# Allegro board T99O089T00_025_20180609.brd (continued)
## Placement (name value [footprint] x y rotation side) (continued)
C118  47uF  [C-0805-H1_35]  269.66 135.65 90 top
C119  1uF  [S-C-0402]  206.9 173.93 0 top
C120  0.1uF  [S-C-0402]  203.54 173.93 0 bottom
C121  0.1uF  [S-C-0402]  202.58 173.93 0 bottom
C122  1nF  [S-C-0402]  208.37 173.93 180 bottom
C123  0.1uF  [S-C-0402]  210.76 173.93 180 top
C124  1uF  [S-C-0402]  207.86 173.93 0 top
C125  0.1uF  [S-C-0402]  212.69 173.93 180 top
C126  0.1uF  [S-C-0402]  206.44 173.93 0 bottom
C127  1nF  [S-C-0402]  211.27 173.93 180 bottom
C128  0.1uF  [S-C-0402]  201.61 173.93 0 bottom
C129  1uF  [S-C-0402]  201.61 173.93 0 top
C130  0.1uF  [S-C-0402]  219.45 173.93 180 top
C131  0.1uF  [S-C-0402]  217.06 173.93 0 bottom
C132  1nF  [S-C-0402]  210.3 173.93 180 bottom
C133  0.1uF  [S-C-0402]  216.55 173.93 180 top
C134  1uF  [S-C-0402]  239.37 173.93 0 top
C135  0.1uF  [S-C-0402]  215.13 173.93 0 bottom
C136  0.1uF  [S-C-0402]  214.62 173.93 180 top
C137  1nF  [S-C-0402]  213.2 173.93 180 bottom
C138  0.1uF  [S-C-0402]  219.95 173.93 0 bottom
C139  47uF  [C-0805-H1_35]  231.79 173.49 180 top
C140  1uF  [S-C-0402]  230.23 173.93 0 top
C141  0.1uF  [S-C-0402]  231.2 173.93 0 bottom
C142  0.1uF  [S-C-0402]  235.06 173.93 0 bottom
C143  1nF  [S-C-0402]  242.27 173.93 0 top
C144  0.1uF  [S-C-0402]  230.23 173.93 0 bottom
C145  1uF  [S-C-0402]  209.79 173.93 0 top
C146  0.1uF  [S-C-0402]  228.35 173.91 180 top
C147  0.1uF  [S-C-0402]  228.32 173.94 0 bottom
C148  1nF  [S-C-0402]  236.48 173.93 0 top
C149  0.1uF  [S-C-0402]  236.99 173.93 0 bottom
C150  1uF  [S-C-0402]  270.24 131.92 270 top
C151  0.1uF  [S-C-0402]  238.92 173.93 0 bottom
C152  0.1uF  [S-C-0402]  239.88 173.93 0 bottom
C153  1nF  [S-C-0402]  229.29 173.91 0 top
C154  0.1uF  [S-C-0402]  232.16 173.93 0 bottom
C155  1uF  [S-C-0402]  244.2 173.93 0 top
C156  0.1uF  [S-C-0402]  235.51 173.93 180 top
C157  0.1uF  [S-C-0402]  270.24 118.41 90 top
C158  1nF  [S-C-0402]  270.24 128.52 90 bottom
C159  0.1uF  [S-C-0402]  244.71 173.93 0 bottom
C160  47uF  [C-0805-H1_35]  203.17 173.48 180 top
C161  1uF  [S-C-0402]  238.41 173.93 0 top
C162  0.1uF  [S-C-0402]  242.78 173.93 0 bottom
C163  0.1uF  [S-C-0402]  270.24 126.13 90 top
C164  1nF  [S-C-0402]  270.24 127.55 90 bottom
C165  0.1uF  [S-C-0402]  270.24 135.27 270 bottom
C166  1uF  [S-C-0402]  270.24 137.2 270 top
C167  0.1uF  [S-C-0402]  270.24 137.2 270 bottom
C168  0.1uF  [S-C-0402]  270.24 136.24 270 bottom
C169  1nF  [S-C-0402]  270.24 125.62 90 bottom
C170  0.1uF  [S-C-0402]  270.24 132.38 270 bottom
C171  1uF  [S-C-0402]  270.24 129.02 270 top
C172  0.1uF  [S-C-0402]  270.24 121.3 90 top
C173  0.1uF  [S-C-0402]  270.24 121.76 270 bottom
C174  1nF  [S-C-0402]  241.3 173.93 0 top
C175  0.1uF  [S-C-0402]  270.24 118.86 270 bottom
C176  1uF  [S-C-0402]  270.24 130.96 270 top
C177  0.1uF  [S-C-0402]  270.24 124.2 90 top
C178  0.1uF  [S-C-0402]  270.24 128.06 90 top
C179  1nF  [S-C-0402]  270.24 130.45 90 bottom
C180  0.1uF  [S-C-0402]  270.24 123.69 270 bottom
C181  47uF  [C-0805-H1_35]  205.32 173.48 0 top
C182  1uF  [S-C-0402]  216.09 173.93 0 bottom
C183  0.1uF  [S-C-0402]  245.17 173.93 0 top
C184  0.1uF  [S-C-0402]  270.24 120.34 270 top
C185  1nF  [S-C-0402]  205.48 173.93 0 bottom
C186  0.1uF  [S-C-0402]  270.24 122.27 270 top
C187  1uF  [S-C-0402]  217.51 173.93 180 top
C188  0.1uF  [S-C-0402]  218.48 173.93 0 top
C189  0.1uF  [S-C-0402]  214.16 173.93 180 bottom
C190  1nF  [S-C-0402]  200.65 173.93 0 bottom
C191  0.1uF  [S-C-0402]  246.13 173.93 0 top
C192  1uF  [S-C-0402]  200.65 173.93 180 top
C193  0.1uF  [S-C-0402]  247.09 173.94 0 top
C194  0.1uF  [S-C-0402]  233.13 173.93 180 bottom
C195  1nF  [S-C-0402]  199.68 173.93 0 bottom
C196  0.1uF  [S-C-0402]  234.09 173.93 180 bottom
C197  1uF  [S-C-0402]  199.68 173.93 180 top
C198  0.1uF  [S-C-0402]  240.85 173.93 180 bottom
C199  0.1uF  [S-C-0402]  237.95 173.93 180 bottom
C200  1nF  [S-C-0402]  229.26 173.94 0 bottom
C201  0.1uF  [S-C-0402]  218.99 173.93 180 bottom
C202  47uF  [C-0805-H1_35]  269.66 133.5 270 top
C203  1uF  [S-C-0402]  240.34 173.93 180 top
C204  0.1uF  [S-C-0402]  230.76 171.07 0 bottom
C205  0.1uF  [S-C-0402]  229.74 171.07 0 bottom
C206  1nF  [S-C-0402]  207.41 173.93 0 bottom
C207  0.1uF  [S-C-0402]  220.41 173.93 0 top
C208  1uF  [S-C-0402]  230.1 171.09 0 top
C209  0.1uF  [S-C-0402]  218.02 173.93 180 bottom
C210  0.1uF  [S-C-0402]  212.23 173.93 180 bottom
C211  1nF  [S-C-0402]  241.81 173.93 0 bottom
C212  0.1uF  [S-C-0402]  213.65 173.93 0 top
C213  1uF  [S-C-0402]  229.08 171.09 0 top
C214  0.1uF  [S-C-0402]  209.34 173.93 180 bottom
C215  0.1uF  [S-C-0402]  208.83 173.93 0 top
C216  1nF  [S-C-0402]  246.64 173.93 0 bottom
C217  0.1uF  [S-C-0402]  204.51 173.93 180 bottom
C218  1uF  [S-C-0402]  270.24 123.23 90 top
C219  0.1uF  [S-C-0402]  270.24 134.31 90 bottom
C220  0.1uF  [S-C-0402]  270.24 127.09 270 top
C221  1nF  [S-C-0402]  245.67 173.93 0 bottom
C222  0.1uF  [S-C-0402]  270.24 124.66 90 bottom
C223  47uF  [C-0805-H1_35]  233.94 173.49 0 top
C224  1uF  [S-C-0402]  243.23 173.93 180 top
C225  0.1uF  [S-C-0402]  270.24 120.8 90 bottom
C226  0.1uF  [S-C-0402]  236.02 173.93 180 bottom
C227  1nF  [S-C-0402]  270.24 131.41 270 bottom
C228  0.1uF  [S-C-0402]  215.58 173.93 0 top
C229  1uF  [S-C-0402]  270.24 129.99 90 top
C230  0.1uF  [S-C-0402]  211.72 173.93 0 top
C231  0.1uF  [S-C-0402]  270.24 129.48 90 bottom
C232  1nF  [S-C-0402]  270.24 139.13 270 bottom
C233  0.1uF  [S-C-0402]  270.24 119.83 90 bottom
C234  1uF  [S-C-0402]  270.24 139.13 90 top
C235  0.1uF  [S-C-0402]  270.24 126.59 90 bottom
C236  0.1uF  [S-C-0402]  270.24 125.16 270 top
C237  1nF  [S-C-0402]  270.24 138.17 270 bottom
C238  0.1uF  [S-C-0402]  270.24 119.37 270 top
C239  1uF  [S-C-0402]  270.24 138.17 90 top
C240  0.1uF  [S-C-0402]  270.24 122.73 90 bottom
C241  0.1uF  [S-C-0402]  237.44 173.93 0 top
C242  1nF  [S-C-0402]  270.24 133.34 270 bottom
C243  0.1uF  [S-C-0402]  243.74 173.93 180 bottom
C244  330uF  [C-TAN-S7_3X4_3-H2]  185.29 101.02 270 top
C245  47uF  [C-0805-H1_35]  239.31 112.58 0 top
C246  1uF  [S-C-0402]  205.36 119.5 0 bottom
C247  0.1uF  [S-C-0402]  219.36 125.5 0 bottom
C248  0.1uF  [S-C-0402]  221.36 127.5 0 bottom
C249  1nF  [S-C-0402]  209.36 124.5 0 bottom
C250  1uF  [S-C-0402]  206.36 119.5 180 bottom
C251  0.1uF  [S-C-0402]  222.36 118.5 0 bottom
C252  1nF  [S-C-0402]  205.86 115 270 bottom
C253  0.1uF  [S-C-0402]  218.86 115 90 bottom
C254  1uF  [S-C-0402]  212.36 133.5 180 bottom
C255  0.1uF  [S-C-0402]  246.32 160.04 180 bottom
C256  0.1uF  [S-C-0402]  254.09 117.89 270 bottom
C257  1nF  [S-C-0402]  218.37 133.5 0 bottom
C258  1uF  [S-C-0402]  205.66 153.64 90 bottom
C259  0.1uF  [S-C-0402]  246.83 155.72 90 bottom
C260  1nF  [S-C-0402]  207.73 155.72 270 bottom
C261  0.1uF  [S-C-0402]  246.32 158.26 0 bottom
C262  47uF  [C-0805-H1_35]  266.43 121.23 0 top
C263  330uF  [C-TAN-S7_3X4_3-H2]  185.29 106.36 270 top
C264  22uF  [C-0805]  191.77 103.43 0 top
C265  0.1uF  [S-C-0402]  214.86 125.99 270 bottom
C266  0.1uF  [S-C-0402]  217.36 127.5 0 bottom
C267  0.1uF  [S-C-0402]  218.36 123.5 180 bottom
C268  1uF  [S-C-0402]  208.36 122.5 180 bottom
C269  0.1uF  [S-C-0402]  217.36 123.5 0 bottom
C270  0.1uF  [S-C-0402]  216.36 123.5 180 bottom
C271  1nF  [S-C-0402]  212.36 122.5 180 bottom
C272  0.1uF  [S-C-0402]  214.36 123.5 0 bottom
C273  0.1uF  [S-C-0402]  218.36 121.5 180 bottom
C274  0.1uF  [S-C-0402]  234.66 155.72 90 bottom
C275  0.1uF  [S-C-0402]  229.36 131.5 180 bottom
C276  330uF  [C-TAN-S7_3X4_3-H2]  194.2 142.01 90 bottom
C277  1uF  [S-C-0402]  209.36 116.5 180 bottom
C278  1nF  [S-C-0402]  212.36 117.5 0 bottom
C279  0.1uF  [S-C-0402]  218.36 118.5 0 bottom
C280  1uF  [S-C-0402]  211.43 153.64 270 bottom
C281  0.1uF  [S-C-0402]  229.36 134.5 180 bottom
C282  0.1uF  [S-C-0402]  230.84 160.71 270 bottom
C283  1nF  [S-C-0402]  219.37 135.5 0 bottom
C284  0.1uF  [S-C-0402]  232.58 153.64 270 bottom
C285  1uF  [S-C-0402]  211.86 136 90 bottom
C286  0.1uF  [S-C-0402]  231.36 126.5 180 bottom
C287  0.1uF  [S-C-0402]  229.36 125.5 180 bottom
C288  1nF  [S-C-0402]  220.37 131.5 0 bottom
C289  0.1uF  [S-C-0402]  222.36 135.5 180 bottom
C290  47uF  [C-0805-H1_35]  208.69 139.68 270 bottom
C291  0.1uF  [S-C-0402]  213.36 124.5 180 bottom
C292  1uF  [S-C-0402]  205.36 123.5 180 bottom
C293  0.1uF  [S-C-0402]  212.86 121 90 bottom
C294  0.1uF  [S-C-0402]  211.36 122.5 180 bottom
C295  1nF  [S-C-0402]  210.36 117.5 0 bottom
C296  0.1uF  [S-C-0402]  210.36 124.5 0 bottom
C297  1uF  [S-C-0402]  206.36 123.5 180 bottom
C298  0.1uF  [S-C-0402]  212.36 124.5 0 bottom
C299  0.1uF  [S-C-0402]  210.86 121 90 bottom
C300  1nF  [S-C-0402]  210.36 122.5 180 bottom
C301  0.1uF  [S-C-0402]  213.36 122.5 180 bottom
C302  1uF  [S-C-0402]  227.36 127.5 0 bottom
C303  0.1uF  [S-C-0402]  217.37 137.5 180 bottom
C304  0.1uF  [S-C-0402]  216.86 135 90 bottom
C305  1nF  [S-C-0402]  225.42 157.04 0 bottom
C306  0.1uF  [S-C-0402]  215.86 131 90 bottom
C307  1uF  [S-C-0402]  226.36 125.5 0 bottom
C308  0.1uF  [S-C-0402]  216.37 129.5 180 bottom
C309  0.1uF  [S-C-0402]  217.37 131.5 180 bottom
C310  1nF  [S-C-0402]  226.18 153.64 270 bottom
C311  0.1uF  [S-C-0402]  215.37 133.5 180 bottom
C312  47uF  [C-0805-H1_35]  203.23 139.68 270 bottom
C313  1uF  [S-C-0402]  225.86 124 90 bottom
C314  0.1uF  [S-C-0402]  210.39 159.54 270 bottom
C315  0.1uF  [S-C-0402]  210.09 156.66 270 bottom
C316  1nF  [S-C-0402]  226.36 131.5 0 bottom
C317  0.1uF  [S-C-0402]  212.23 160.77 90 bottom
C318  1uF  [S-C-0402]  217.83 153.64 90 bottom
C319  0.1uF  [S-C-0402]  210.45 160.54 270 bottom
C320  0.1uF  [S-C-0402]  210.37 137.5 180 bottom
C321  1nF  [S-C-0402]  226.98 160.85 90 bottom
C322  0.1uF  [S-C-0402]  210.36 135.5 0 bottom
C323  47uF  [C-0805-H1_35]  217.58 139.68 270 bottom
C324  330uF  [C-TAN-S7_3X4_3-H2]  192.63 161.81 0 top
C325  330uF  [C-TAN-S7_3X4_3-H2]  185.29 111.69 270 top
C326  47uF  [C-0805-H1_35]  191.77 112.25 0 top
C327  1uF  [S-C-0402]  217.36 119.5 180 bottom
C328  0.1uF  [S-C-0402]  211.86 115 270 bottom
C329  0.1uF  [S-C-0402]  211.86 116 90 bottom
C330  1nF  [S-C-0402]  215.36 123.5 0 bottom
C331  0.1uF  [S-C-0402]  211.36 117.5 0 bottom
C332  1uF  [S-C-0402]  217.36 117.5 180 bottom
C333  0.1uF  [S-C-0402]  212.36 119.5 180 bottom
C334  0.1uF  [S-C-0402]  210.36 119.5 180 bottom
C335  1nF  [S-C-0402]  211.36 124.5 0 bottom
C336  0.1uF  [S-C-0402]  211.36 119.5 0 bottom
C337  1uF  [S-C-0402]  227.36 133.5 0 bottom
C338  0.1uF  [S-C-0402]  206.86 136 270 bottom
C339  0.1uF  [S-C-0402]  207.23 160.04 180 bottom
C340  1nF  [S-C-0402]  225.42 159.94 0 bottom
C341  0.1uF  [S-C-0402]  207.23 158.26 0 bottom
C342  1uF  [S-C-0402]  225.36 126.5 180 bottom
C343  0.1uF  [S-C-0402]  205.79 160.71 90 bottom
C344  0.1uF  [S-C-0402]  206.37 133.5 0 bottom
C345  1nF  [S-C-0402]  227.86 124 90 bottom
C346  0.1uF  [S-C-0402]  207.36 137.5 180 bottom
C347  47uF  [C-0805-H1_35]  212.62 139.68 90 bottom
C348  330uF  [C-TAN-S7_3X4_3-H2]  245.62 107.5 90 top
C349  22uF  [C-0805]  239.5 105.51 180 top
C350  1uF  [S-C-0402]  214.86 122 90 bottom
C351  0.1uF  [S-C-0402]  209.36 127.5 180 bottom
C352  0.1uF  [S-C-0402]  206.36 117.5 180 bottom
C353  1nF  [S-C-0402]  222.36 114.5 180 bottom
C354  0.1uF  [S-C-0402]  209.36 119.5 0 bottom
C355  1uF  [S-C-0402]  214.86 118 90 bottom
C356  0.1uF  [S-C-0402]  209.36 122.5 180 bottom
C357  0.1uF  [S-C-0402]  207.36 122.5 180 bottom
C358  1nF  [S-C-0402]  218.36 127.5 0 bottom
C359  0.1uF  [S-C-0402]  208.86 115 90 bottom
C360  1uF  [S-C-0402]  226.36 137.49 0 bottom
C361  0.1uF  [S-C-0402]  201.37 135.5 0 bottom
C362  0.1uF  [S-C-0402]  208.86 132 90 bottom
C363  1nF  [S-C-0402]  229.36 128.5 0 bottom
C364  0.1uF  [S-C-0402]  208.36 133.5 180 bottom
C365  1uF  [S-C-0402]  227.36 135.5 0 bottom
C366  0.1uF  [S-C-0402]  203.37 133.5 0 bottom
C367  0.1uF  [S-C-0402]  251.55 129.05 0 bottom
C368  1nF  [S-C-0402]  231.36 132.5 0 bottom
C369  0.1uF  [S-C-0402]  254.09 129.56 270 bottom
C370  47uF  [C-0805-H1_35]  216.8 170.6 90 top
C371  0.1uF  [S-C-0402]  221.36 125.5 0 bottom
C372  1uF  [S-C-0402]  219.36 119.5 180 bottom
C373  0.1uF  [S-C-0402]  220.36 123.5 180 bottom
C374  0.1uF  [S-C-0402]  219.36 123.5 0 bottom
C375  1nF  [S-C-0402]  222.36 121.5 0 bottom
C376  0.1uF  [S-C-0402]  219.36 127.5 0 bottom
C377  1uF  [S-C-0402]  221.36 115.5 0 bottom
C378  0.1uF  [S-C-0402]  222.36 127.5 0 bottom
C379  0.1uF  [S-C-0402]  217.36 125.5 0 bottom
C380  1nF  [S-C-0402]  220.36 115.5 0 bottom
C381  0.1uF  [S-C-0402]  219.36 116.5 180 bottom
C382  1UF  [S-C-0402]  198.86 128 270 bottom
C383  0.1uF  [S-C-0402]  201.36 127.5 0 bottom
C384  0.1uF  [S-C-0402]  199.36 133.5 180 bottom
C385  1nF  [S-C-0402]  196.86 127 270 bottom
C386  0.1uF  [S-C-0402]  201.36 122.5 0 bottom
C387  1UF  [S-C-0402]  196.86 122 270 bottom
C388  22uF  [C-0805]  185.95 112.26 0 bottom
C389  330uF  [C-TAN-S7_3X4_3-H2]  245.75 102.11 90 top
C390  47uF  [C-0805-H1_35]  239.5 102.11 0 top
C391  1uF  [S-C-0402]  216.36 125.5 0 bottom
C392  0.1uF  [S-C-0402]  216.36 118.5 0 bottom
C393  0.1uF  [S-C-0402]  216.36 116.5 0 bottom
C394  1nF  [S-C-0402]  220.36 125.5 0 bottom
C395  0.1uF  [S-C-0402]  215.36 116.5 180 bottom
C396  1uF  [S-C-0402]  221.36 121.5 180 bottom
C397  0.1uF  [S-C-0402]  214.36 116.5 0 bottom
C398  0.1uF  [S-C-0402]  215.86 115 270 bottom
C399  1nF  [S-C-0402]  220.36 127.5 0 bottom
C400  0.1uF  [S-C-0402]  218.36 116.5 0 bottom
C401  0.1uF  [S-C-0402]  196.36 130.5 0 bottom
C402  0.1uF  [S-C-0402]  197.36 135.5 180 bottom
C403  0.1uF  [S-C-0402]  204.36 122.5 0 bottom
C404  1nF  [S-C-0402]  203.86 124 270 bottom
C405  0.1uF  [S-C-0402]  205.36 125.5 0 bottom
C406  10uF  [S-C-0402]  204.36 125.5 0 bottom
C407  330uF  [C-TAN-S7_3X4_3-H2]  245.62 113.36 90 top
C408  22uF  [C-0805]  191.77 107.37 180 top
C409  1uF  [S-C-0402]  219.36 121.5 180 bottom
C410  0.1uF  [S-C-0402]  214.36 114.5 0 bottom
C411  0.1uF  [S-C-0402]  217.36 115.5 0 bottom
C412  1nF  [S-C-0402]  220.36 121.5 0 bottom
C413  0.1uF  [S-C-0402]  210.36 127.5 0 bottom
C414  1uF  [S-C-0402]  222.86 116 90 bottom
C415  0.1uF  [S-C-0402]  211.36 127.5 180 bottom
C416  0.1uF  [S-C-0402]  213.36 126.5 180 bottom
C417  1nF  [S-C-0402]  218.36 125.5 0 bottom
C418  0.1uF  [S-C-0402]  223.36 118.5 0 bottom
C419  0.1uF  [S-C-0402]  203.36 126.5 0 bottom
C420  10uF  [S-C-0402]  204.36 127.5 180 bottom
C421  0.1uF  [S-C-0402]  193.76 133.88 90 bottom
C422  330uF  [C-TAN-S7_3X4_3-H2]  201.42 93.53 0 bottom
C423  330uF  [C-TAN-S7_3X4_3-H2]  217.11 90.1 270 bottom
C424  47uF  [C-0805-H1_35]  210.82 99.37 90 bottom
C425  1UF  [S-C-0402]  211.36 111.5 0 bottom
C426  0.1uF  [S-C-0402]  221.86 103 270 bottom
C427  0.1uF  [S-C-0402]  222.36 106.5 0 bottom
C428  1nF  [S-C-0402]  217.86 103 90 bottom
C429  0.1uF  [S-C-0402]  219.36 109.5 0 bottom
C430  0.1uF  [S-C-0402]  215.86 111 90 bottom
C431  0.1uF  [S-C-0402]  215.36 108.5 180 bottom
C432  1nF  [S-C-0402]  217.86 101 90 bottom
C433  0.1uF  [S-C-0402]  216.36 109.5 0 bottom
C434  1nF  [S-C-0402]  213.87 103.05 0 bottom
C435  0.1uF  [S-C-0402]  221.86 101 270 bottom
C436  1uF  [S-C-0402]  225.86 113 90 bottom
C437  0.1uF  [S-C-0402]  228.36 103.5 0 bottom
C438  1nF  [S-C-0402]  230.86 108 90 bottom
C439  1uF  [S-C-0402]  231.36 113.5 180 bottom
C440  0.1uF  [S-C-0402]  225.86 101 270 bottom
C441  0.1uF  [S-C-0402]  227.36 110.5 180 bottom
C442  1nF  [S-C-0402]  225.86 115 270 bottom
C443  330uF  [C-TAN-S7_3X4_3-H2]  238.68 102.02 270 bottom
C444  0.1uF  [S-C-0402]  226.86 108 270 bottom
C445  1nF  [S-C-0402]  224.86 114 90 bottom
C446  1uF  [S-C-0402]  224.36 118.5 180 bottom
C447  0.1uF  [S-C-0402]  225.86 103 270 bottom
C448  0.1uF  [S-C-0402]  229.86 101 270 bottom
C449  0.1uF  [S-C-0402]  226.86 106 270 bottom
C450  0.1uF  [S-C-0402]  226.86 117 270 bottom
C451  47uF  [C-0805-H1_35]  236.22 105.9 90 bottom
C452  47uF  [C-0805-H1_35]  215.9 99.37 90 bottom
C453  47uF  [C-0805-H1_35]  219.96 99.37 90 bottom
C454  1UF  [S-C-0402]  210.36 108.5 0 bottom
C455  0.1uF  [S-C-0402]  210.36 106.5 0 bottom
C456  0.1uF  [S-C-0402]  211.36 109.5 0 bottom
C457  1nF  [S-C-0402]  222.36 108.5 0 bottom
C458  0.1uF  [S-C-0402]  210.86 101 90 bottom
C459  1UF  [S-C-0402]  223.86 111 270 bottom
C460  0.1uF  [S-C-0402]  208.86 103 270 bottom
C461  0.1uF  [S-C-0402]  215.86 101 90 bottom
C462  1nF  [S-C-0402]  223.36 109.5 180 bottom
C463  0.1uF  [S-C-0402]  214.36 106.5 0 bottom
C464  1nF  [S-C-0402]  219.36 111.5 0 bottom
C465  0.1uF  [S-C-0402]  218.36 106.5 0 bottom
C466  1UF  [S-C-0402]  218.36 108.5 0 bottom
C467  330uF  [C-TAN-S7_3X4_3-H2]  206.88 93.53 0 bottom
C468  1uF  [S-C-0402]  226.35 118.5 0 bottom
C469  1nF  [S-C-0402]  229.36 118.5 180 bottom
C470  1uF  [S-C-0402]  233.36 114.5 0 bottom
C471  0.1uF  [S-C-0402]  229.86 103 270 bottom
C472  1nF  [S-C-0402]  229.36 114.5 180 bottom
C473  1uF  [S-C-0402]  231.36 118.5 0 bottom
C474  0.1uF  [S-C-0402]  231.36 106.5 0 bottom
C475  0.1uF  [S-C-0402]  227.86 105 90 bottom
C476  1nF  [S-C-0402]  233.36 118.5 0 bottom
C477  0.1uF  [S-C-0402]  231.86 105 270 bottom
C478  0.1uF  [S-C-0402]  228.36 117.5 0 bottom
C479  47uF  [C-0805-H1_35]  236.22 109.96 90 bottom
C480  1uF  [S-C-0402]  230.86 115 270 bottom
C481  0.1uF  [S-C-0402]  228.86 108 90 bottom
C482  1nF  [S-C-0402]  232.36 110.5 0 bottom
C483  1uF  [S-C-0402]  227.86 113 270 bottom
C484  0.1uF  [S-C-0402]  230.36 106.5 0 bottom
C485  0.1uF  [S-C-0402]  232.36 103.5 0 bottom
C486  1nF  [S-C-0402]  231.36 116.5 180 bottom
C487  0.1uF  [S-C-0402]  231.36 110.5 180 bottom
C488  0.1uF  [S-C-0402]  228.36 110.5 180 bottom
C489  47uF  [C-0805-H1_35]  236.22 107.93 90 bottom
C490  330uF  [C-TAN-S7_3X4_3-H2]  233.3 88.27 270 bottom
C491  330uF  [C-TAN-S7_3X4_3-H2]  225.91 95.2 270 bottom
C492  47uF  [C-0805-H1_35]  226.13 99.47 90 bottom
C493  1uF  [S-C-0402]  224.36 103.5 180 bottom
C494  0.1uF  [S-C-0402]  216.36 103.5 0 bottom
C495  0.1uF  [S-C-0402]  209.86 105 270 bottom
C496  1nF  [S-C-0402]  211.36 102.5 180 bottom
C497  0.1uF  [S-C-0402]  220.36 103.5 0 bottom
C498  1uF  [S-C-0402]  215.36 104.5 0 bottom
C499  0.1uF  [S-C-0402]  220.36 105.5 180 bottom
C500  0.1uF  [S-C-0402]  224.36 105.5 180 bottom
C501  1nF  [S-C-0402]  211.86 105 270 bottom
C502  0.1uF  [S-C-0402]  216.36 105.5 180 bottom
C503  1nF  [S-C-0402]  223.36 104.5 0 bottom
C504  0.1uF  [S-C-0402]  219.36 105.5 180 bottom
C505  10uF  [S-C-0402]  196.36 116.5 0 bottom
C506  1uF  [S-C-0402]  197.36 117.5 180 bottom
C507  0.1uF  [S-C-0402]  198.86 118 90 bottom
C508  0.1uF  [S-C-0402]  198.86 119 90 bottom
C509  1nF  [S-C-0402]  196.86 119 90 bottom
C510  22uF  [C-0805]  194.65 117.37 0 bottom
C511  0.1uF  [S-C-0402]  257.17 85.85 0 bottom
C512  330uF  [C-TAN-S7_3X4_3-H2]  241.35 88.49 180 bottom
C513  330uF  [C-TAN-S7_3X4_3-H2]  187.58 97.34 90 bottom
C514  47uF  [C-0805-H1_35]  194.56 103.43 180 bottom
C515  1uF  [S-C-0402]  204.36 109.5 0 bottom
C516  0.1uF  [S-C-0402]  197.86 105 90 bottom
C517  0.1uF  [S-C-0402]  200.36 109.5 180 bottom
C518  1nF  [S-C-0402]  198.86 101 270 bottom
C519  0.1uF  [S-C-0402]  196.36 102.5 0 bottom
C520  1uF  [S-C-0402]  198.86 108 270 bottom
C521  0.1uF  [S-C-0402]  196.36 104.5 180 bottom
C522  0.1uF  [S-C-0402]  206.86 103 90 bottom
C523  1nF  [S-C-0402]  195.36 112.5 180 bottom
C524  0.1uF  [S-C-0402]  197.36 115.5 180 bottom
C525  1nF  [S-C-0402]  196.86 110 270 bottom
C526  0.1uF  [S-C-0402]  198.86 114 90 bottom
C527  1uF  [S-C-0402]  195.4 120.54 0 bottom
C528  0.1uF  [S-C-0402]  196.86 120 90 bottom
C529  10uF  [C-0603S0]  194.15 120.8 180 bottom
C530  0.1uF  [S-C-0402]  254.67 100.65 180 bottom
C531  47uF  [C-0805-H1_35]  198.88 99.37 90 bottom
C532  47uF  [C-0805-H1_35]  194.69 106.86 0 bottom
C533  1uF  [S-C-0402]  196.36 108.5 180 bottom
C534  0.1uF  [S-C-0402]  201.86 106 90 bottom
C535  0.1uF  [S-C-0402]  204.36 104.5 180 bottom
C536  1nF  [S-C-0402]  197.86 106 270 bottom
C537  0.1uF  [S-C-0402]  200.86 101 270 bottom
C538  1uF  [S-C-0402]  205.86 110 270 bottom
C539  0.1uF  [S-C-0402]  199.36 115.5 180 bottom
C540  0.1uF  [S-C-0402]  205.86 106 90 bottom
C541  1nF  [S-C-0402]  200.36 104.5 0 bottom
C542  0.1uF  [S-C-0402]  202.36 108.5 180 bottom
C543  1nF  [S-C-0402]  198.86 103 270 bottom
C544  0.1uF  [S-C-0402]  201.86 110 90 bottom
C545  1uF  [S-C-0402]  216.86 122 90 bottom
C546  0.1uF  [S-C-0402]  216.86 121 90 bottom
C547  10uF  [C-0603S0]  234.4 120.8 180 bottom
C548  0.1uF  [S-C-0402]  5.11 80.31 90 top
C549  47uF  [C-0805-H1_35]  206.75 99.37 90 bottom
C550  47uF  [C-0805-H1_35]  202.82 99.37 90 bottom
C551  1uF  [S-C-0402]  202.86 115 90 bottom
C552  0.1uF  [S-C-0402]  202.86 113 90 bottom
C553  0.1uF  [S-C-0402]  204.36 107.5 0 bottom
C554  1nF  [S-C-0402]  202.86 103 270 bottom
C555  0.1uF  [S-C-0402]  206.86 101 90 bottom
C556  1uF  [S-C-0402]  200.86 114 90 bottom
C557  0.1uF  [S-C-0402]  206.86 108 90 bottom
C558  0.1uF  [S-C-0402]  200.86 113 270 bottom
C559  1nF  [S-C-0402]  201.86 105 270 bottom
C560  0.1uF  [S-C-0402]  204.86 114 90 bottom
C561  1nF  [S-C-0402]  197.36 113.5 180 bottom
C562  0.1uF  [S-C-0402]  205.86 105 90 bottom
C563  330uF  [C-TAN-S7_3X4_3-H2]  250.91 112.98 270 bottom
C564  330uF  [C-TAN-S7_3X4_3-H2]  241.94 125.45 0 bottom
C565  47uF  [C-0805-H1_35]  236.58 118.4 270 bottom
C566  1uF  [S-C-0402]  220.36 113.5 0 bottom
C567  0.1uF  [S-C-0402]  228.36 121.5 180 bottom
C568  0.1uF  [S-C-0402]  205.36 111.5 0 bottom
C569  1nF  [S-C-0402]  203.86 121 90 bottom
C570  0.1uF  [S-C-0402]  207.36 113.5 180 bottom
C571  1uF  [S-C-0402]  206.36 111.5 180 bottom
C572  0.1uF  [S-C-0402]  216.36 113.5 180 bottom
C573  0.1uF  [S-C-0402]  212.36 111.5 0 bottom
C574  1nF  [S-C-0402]  213.36 113.5 0 bottom
C575  0.1uF  [S-C-0402]  205.36 121.5 180 bottom
C576  1nF  [S-C-0402]  212.36 113.5 0 bottom
C577  0.1uF  [S-C-0402]  208.36 111.5 0 bottom
C578  1uF  [S-C-0402]  200.36 121.5 180 bottom
C579  0.1uF  [S-C-0402]  201.86 121 90 bottom
C580  10uF  [C-0603S0]  187.02 105.12 0 bottom
C581  0.1uF  [S-C-0402]  181.19 140.35 270 top
C582  1uF  [S-C-0402]  206.36 113.5 0 bottom
C583  0.1uF  [S-C-0402]  216.86 112 90 bottom
C584  0.1uF  [S-C-0402]  222.36 112.5 0 bottom
C585  1nF  [S-C-0402]  207.36 111.5 180 bottom
C586  0.1uF  [S-C-0402]  220.86 112 90 bottom
C587  1uF  [S-C-0402]  221.36 113.5 0 bottom
C588  0.1uF  [S-C-0402]  215.36 113.5 180 bottom
C589  0.1uF  [S-C-0402]  214.86 112 270 bottom
C590  1nF  [S-C-0402]  227.36 121.5 0 bottom
C591  0.1uF  [S-C-0402]  223.86 113 90 bottom
C592  1nF  [S-C-0402]  217.36 113.5 0 bottom
C593  0.1uF  [S-C-0402]  223.86 112 90 bottom
C594  1uF  [S-C-0402]  207.86 126 270 bottom
C595  0.1uF  [S-C-0402]  206.36 125.5 0 bottom
C596  10uF  [C-0603S0]  194.78 130.45 180 bottom
C597  0.1uF  [S-C-0402]  184.23 105.05 180 bottom
C598  1uF  [S-C-0402]  208.86 114 90 bottom
C599  0.1uF  [S-C-0402]  210.36 113.5 180 bottom
C600  10uF  [C-0603S0]  194.02 110.97 180 bottom
C601  0.1uF  [S-C-0402]  191.22 111.14 0 bottom
C602  1uF  [S-C-0402]  207.36 124.5 180 bottom
C603  0.1uF  [S-C-0402]  208.36 124.5 0 bottom
C604  10uF  [C-0603S0]  193.64 136.29 180 bottom
C605  0.1uF  [S-C-0402]  191.35 113.43 180 bottom
C606  1uF  [S-C-0402]  207.36 119.5 0 bottom
C607  0.1uF  [S-C-0402]  208.36 118.5 180 bottom
C608  10uF  [C-0603S0]  191.99 127.91 180 bottom
C609  0.1uF  [S-C-0402]  189.32 128.04 0 bottom
C610  1uF  [S-C-0402]  201.36 116.5 180 bottom
C611  0.1uF  [S-C-0402]  202.36 116.5 0 bottom
C612  10uF  [C-0603S0]  194.02 113.56 0 bottom
C613  0.1uF  [S-C-0402]  189.94 140.05 180 top
C614  1uF  [S-C-0402]  220.36 117.5 0 bottom
C615  0.1uF  [S-C-0402]  221.86 117 90 bottom
C616  10uF  [C-0603S0]  236.18 115.46 180 bottom
C617  0.1uF  [S-C-0402]  190.84 136.42 0 bottom
C627  0.1uF  [S-C-0402]  210.67 155.07 180 bottom
C628  0.1uF  [S-C-0402]  210.72 161.93 180 bottom
C632  1uF  [S-C-0402]  207.26 161.93 0 bottom
C633  0.1uF  [S-C-0402]  210.59 163.7 180 bottom
C634  1uF  [S-C-0402]  207.73 156.73 270 bottom
C635  0.1uF  [S-C-0402]  213.77 159.89 180 bottom
C636  1nF  [S-C-0402]  198.48 163.12 0 bottom
C637  22uF  [C-0805]  241.48 199.32 270 top
C651  47uF  [C-0805-H1_35]  256.41 128.04 270 bottom
C652  1uF  [S-C-0402]  203.98 155.7 0 bottom
C653  0.1uF  [S-C-0402]  198.48 155.07 180 bottom
C654  0.1uF  [S-C-0402]  216.19 155.83 180 bottom
C655  1nF  [S-C-0402]  225.47 163.83 0 bottom
C656  0.1uF  [S-C-0402]  212.32 167.73 90 bottom
C657  1uF  [S-C-0402]  234.05 161.93 0 bottom
C658  0.1uF  [S-C-0402]  219.45 167.32 180 bottom
C659  0.1uF  [S-C-0402]  219.43 161.93 180 bottom
C660  1nF  [S-C-0402]  207.23 166.75 0 bottom
C661  0.1uF  [S-C-0402]  219.91 156.73 90 bottom
C665  0.1uF  [S-C-0402]  235.18 160.88 0 bottom
C666  1uF  [S-C-0402]  234.66 156.73 270 bottom
C667  0.1uF  [S-C-0402]  228.52 159.89 180 bottom
C668  0.1uF  [S-C-0402]  229.46 159.89 180 bottom
C669  1nF  [S-C-0402]  202.03 159.5 270 bottom
C670  0.1uF  [S-C-0402]  225.42 155.07 180 bottom
C671  1uF  [S-C-0402]  230.9 155.7 0 bottom
C672  0.1uF  [S-C-0402]  219.46 165.46 0 bottom
C673  0.1uF  [S-C-0402]  237.14 167.31 270 bottom
C674  1nF  [S-C-0402]  198.48 161.36 0 bottom
C675  0.1uF  [S-C-0402]  237.64 161.93 180 bottom
C686  0.1uF  [S-C-0402]  234.03 167.13 180 bottom
C687  1uF  [S-C-0402]  208.28 161.93 0 bottom
C688  0.1uF  [S-C-0402]  246.83 156.73 90 bottom
C689  0.1uF  [S-C-0402]  243.12 155.83 180 bottom
C690  1nF  [S-C-0402]  252.56 129.05 180 bottom
C691  0.1uF  [S-C-0402]  198.96 168.27 180 bottom
C692  1uF  [S-C-0402]  251.53 121.14 270 bottom
C693  0.1uF  [S-C-0402]  202.03 158.55 90 bottom
C694  0.1uF  [S-C-0402]  246.36 166.79 180 bottom
C695  1nF  [S-C-0402]  237.52 163.7 0 bottom
C696  0.1uF  [S-C-0402]  247.4 161.67 180 bottom
C697  1uF  [S-C-0402]  252.56 117.39 180 bottom
C698  0.1uF  [S-C-0402]  246.35 161.93 180 bottom
C699  1nF  [S-C-0402]  225.97 168.31 0 bottom
C700  22uF  [C-0805]  241.48 203.38 90 bottom
C711  1uF  [S-C-0402]  240.58 159.07 180 bottom
C712  0.1uF  [S-C-0402]  251.66 132.77 90 bottom
C713  0.1uF  [S-C-0402]  253.8 132.89 270 bottom
C714  0.1uF  [S-C-0402]  250.9 126.62 90 bottom
C715  0.1uF  [S-C-0402]  257.75 138.24 90 bottom
C716  1nF  [S-C-0402]  225.47 162.07 0 bottom
C724  1uF  [S-C-0402]  237.59 155.07 0 bottom
C735  47uF  [C-0805-H1_35]  241.17 154.32 0 bottom
C736  22uF  [C-0805]  241.48 203.38 270 top
C737  1nF  [S-C-0402]  262.96 118.02 270 bottom
C738  1uF  [S-C-0402]  258.06 129.54 90 bottom
C739  0.1uF  [S-C-0402]  254.5 123.09 0 bottom
C740  1nF  [S-C-0402]  257.9 126.53 270 bottom
C741  1uF  [S-C-0402]  257.43 117.47 180 bottom
C742  0.1uF  [S-C-0402]  250.9 138.29 90 bottom
C743  47uF  [C-0805-H1_35]  202.36 154.81 0 bottom
C744  1uF  [S-C-0402]  258.57 117.47 180 bottom
C745  0.1uF  [S-C-0402]  263.95 137.19 90 bottom
C746  1nF  [S-C-0402]  255.45 123.09 180 bottom
C747  1uF  [S-C-0402]  254.38 135.13 90 bottom
C748  0.1uF  [S-C-0402]  263.58 125 0 bottom
C749  1nF  [S-C-0402]  259.66 126.58 270 bottom
C750  1uF  [S-C-0402]  263.11 129.69 270 bottom
C751  0.1uF  [S-C-0402]  259.53 138.37 90 bottom
C753  100nF  [C-0402S0]  132.41 15.57 270 bottom
C755  1nF  [C-0402S0]  88.35 21.12 180 bottom
C756  1nF  [C-0402S0]  89.72 21.12 180 bottom
C757  1nF  [C-0402S0]  91.1 21.12 180 bottom
C758  1nF  [C-0402S0]  92.47 21.12 180 bottom
C759  1nF  [C-0402S0]  93.33 8.01 0 bottom
C760  1nF  [C-0402S0]  92.06 8.01 0 bottom
C761  1nF  [C-0402S0]  90.78 8.01 0 bottom
C762  1nF  [C-0402S0]  89.51 8.01 0 bottom
C771  100nF  [C-0402S0]  88.24 8.01 180 bottom
C772  100nF  [C-0402S0]  219.07 9.15 180 bottom
C773  1nF  [C-0402S0]  135.63 15.96 180 bottom
C774  1nF  [C-0402S0]  134.57 15.96 180 bottom
C775  1nF  [C-0402S0]  141.95 12.5 90 bottom
C776  1nF  [C-0402S0]  141.95 11.23 90 bottom
C777  1nF  [C-0402S0]  128.95 10.14 270 bottom
C778  1nF  [C-0402S0]  128.95 11.14 270 bottom
C779  1nF  [C-0402S0]  128.95 12.41 270 bottom
C780  1nF  [C-0402S0]  128.95 13.68 270 bottom
C781  1nF  [C-0402S0]  295.48 28.58 270 bottom
C782  1nF  [C-0402S0]  295.48 29.85 270 bottom
C783  1nF  [C-0402S0]  295.48 31.13 270 bottom
C784  1nF  [C-0402S0]  295.48 32.4 270 bottom
C785  1nF  [C-0402S0]  307.09 33.2 90 bottom
C786  1nF  [C-0402S0]  307.09 31.8 90 bottom
C787  1nF  [C-0402S0]  307.09 30.78 90 bottom
C788  1nF  [C-0402S0]  307.09 29.77 90 bottom
C789  100nF  [C-0402S0]  204.78 10.77 90 bottom
C790  100nF  [C-0402S0]  172.41 9.28 180 bottom
C791  1nF  [C-0402S0]  159.79 21.12 180 bottom
C792  1nF  [C-0402S0]  161.06 21.12 180 bottom
C793  1nF  [C-0402S0]  162.33 21.12 180 bottom
C794  1nF  [C-0402S0]  163.6 21.12 180 bottom
C795  1nF  [C-0402S0]  163.57 9.27 0 bottom
C796  1nF  [C-0402S0]  162.3 9.27 0 bottom
C797  1nF  [C-0402S0]  161.03 9.27 0 bottom
C798  1nF  [C-0402S0]  159.76 9.27 0 bottom
C799  1nF  [C-0402S0]  295.48 21.6 270 bottom
C800  1nF  [C-0402S0]  295.48 22.87 270 bottom
C801  1nF  [C-0402S0]  295.48 24.14 270 bottom
C802  1nF  [C-0402S0]  295.48 25.41 270 bottom
C803  1nF  [C-0402S0]  307.09 25.83 90 bottom
C804  1nF  [C-0402S0]  307.09 24.81 90 bottom
C805  1nF  [C-0402S0]  307.09 23.8 90 bottom
C806  1nF  [C-0402S0]  307.09 22.78 90 bottom
C807  100nF  [C-0402S0]  158.57 9.28 180 bottom
C809  1nF  [C-0402S0]  173.63 21.12 180 bottom
C810  1nF  [C-0402S0]  174.9 21.12 180 bottom
C811  1nF  [C-0402S0]  176.18 21.12 180 bottom
C812  1nF  [C-0402S0]  177.45 21.12 180 bottom
C813  1nF  [C-0402S0]  177.42 9.27 0 bottom
C814  1nF  [C-0402S0]  176.14 9.27 0 bottom
C815  1nF  [C-0402S0]  174.87 9.27 0 bottom
C816  1nF  [C-0402S0]  173.6 9.27 0 bottom
C825  100nF  [C-0402S0]  306.83 21.77 270 bottom
C826  1nF  [C-0402S0]  220.29 20.99 180 bottom
C827  1nF  [C-0402S0]  221.56 20.99 180 bottom
C828  1nF  [C-0402S0]  222.83 20.99 180 bottom
C829  1nF  [C-0402S0]  224.1 20.99 180 bottom
C830  1nF  [C-0402S0]  224.07 9.15 0 bottom
C831  1nF  [C-0402S0]  222.8 9.15 0 bottom
C832  1nF  [C-0402S0]  221.53 9.15 0 bottom
C833  1nF  [C-0402S0]  220.26 9.12 0 bottom
C834  100nF  [C-0402S0]  262.77 7.79 180 bottom
C835  1nF  [C-0402S0]  238.44 16.25 270 bottom
C836  1nF  [C-0402S0]  236.59 16.8 90 bottom
C837  1nF  [C-0402S0]  243.7 10.47 90 bottom
C838  1nF  [C-0402S0]  243.7 11.43 90 bottom
C839  1nF  [C-0402S0]  231.9 10.19 270 bottom
C840  1nF  [C-0402S0]  231.9 11.47 270 bottom
C841  1nF  [C-0402S0]  231.9 12.74 270 bottom
C842  1nF  [C-0402S0]  231.9 14.01 270 bottom
C843  100nF  [C-0402S0]  248.67 7.37 180 bottom
C844  100nF  [C-0402S0]  234.6 16.32 90 bottom
C845  1nF  [C-0402S0]  263.99 19.92 180 bottom
C846  1nF  [C-0402S0]  265.26 20.05 180 bottom
C847  1nF  [C-0402S0]  266.53 19.92 180 bottom
C848  1nF  [C-0402S0]  267.8 19.92 180 bottom
C849  1nF  [C-0402S0]  267.77 7.79 0 bottom
C850  1nF  [C-0402S0]  266.5 7.79 0 bottom
C851  1nF  [C-0402S0]  265.23 7.79 0 bottom
C852  1nF  [C-0402S0]  263.96 7.79 0 bottom
C853  100nF  [C-0402S0]  306.83 28.75 270 bottom
C854  0.1uF  [C-0402S0]  140.94 94.04 90 top
C855  0.1uF  [C-0402S0]  140.94 92.89 90 top
C856  0.1uF  [S-C-0402]  278.08 105.08 0 bottom
C857  100uF  [C-1210]  148.15 95.24 270 top
C858  0.1uF  [S-C-0402]  131.71 91.36 180 bottom
C859  0.1uF  [S-C-0402]  125.71 90.36 0 bottom
C860  1nF  [S-C-0402]  136.71 91.36 0 bottom
C861  0.1uF  [S-C-0402]  127.71 90.36 180 bottom
C862  1nF  [S-C-0402]  135.71 91.36 0 bottom
C863  1uF  [S-C-0402]  123.71 91.36 180 bottom
C864  1uF  [S-C-0402]  121.71 91.36 180 bottom
C865  1nF  [S-C-0402]  133.71 91.36 0 bottom
C866  1uF  [S-C-0402]  123.71 104.36 0 bottom
C867  0.1uF  [S-C-0402]  136.21 102.86 270 bottom
C868  1nF  [S-C-0402]  125.71 104.36 0 bottom
C869  0.1uF  [S-C-0402]  134.71 104.36 180 bottom
C870  1nF  [S-C-0402]  127.21 104.86 90 bottom
C871  0.1uF  [S-C-0402]  132.71 104.36 180 bottom
C872  1nF  [S-C-0402]  130.71 104.36 0 bottom
C873  1uF  [S-C-0402]  122.21 103.86 270 bottom
C874  100uF  [C-1210]  140.34 103.84 90 bottom
C875  0.1uF  [S-C-0402]  287.3 104.57 0 bottom
C876  0.1uF  [S-C-0402]  135.2 108.06 0 bottom
C877  47uF  [C-0805-H1_35]  145.21 105.08 0 top
C878  0.1uF  [S-C-0402]  127.21 91.86 270 bottom
C879  1nF  [S-C-0402]  129.21 92.86 270 bottom
C880  0.1uF  [S-C-0402]  129.21 91.86 90 bottom
C881  1uF  [S-C-0402]  127.21 92.86 90 bottom
C882  1nF  [S-C-0402]  129.21 102.86 270 bottom
C883  1uF  [S-C-0402]  127.21 102.86 90 bottom
C884  47uF  [C-0805-H1_35]  128.67 107.86 180 bottom
C885  0.1uF  [S-C-0402]  144.76 109.7 90 bottom
C886  0.1uF  [S-C-0402]  141.08 86.11 0 bottom
C887  330uF  [C-TAN-S7_3X4_3-H2]  132.91 84.36 180 bottom
C888  22uF  [C-0805]  129.02 85.99 0 bottom
C889  0.1uF  [S-C-0402]  125.71 93.36 0 bottom
C890  1nF  [S-C-0402]  135.21 94.86 90 bottom
C891  0.1uF  [S-C-0402]  133.21 95.86 270 bottom
C892  1uF  [S-C-0402]  133.71 100.36 0 bottom
C893  1uF  [S-C-0402]  126.21 99.86 270 bottom
C894  0.1uF  [S-C-0402]  31.59 104.29 180 top
C895  1nF  [S-C-0402]  120.73 128.92 270 bottom
C896  1UF  [S-C-0402]  182.27 112.07 0 bottom
C897  1nF  [S-C-0402]  114.81 127.44 180 bottom
C898  1UF  [S-C-0402]  132.21 94.86 270 bottom
C899  22uF  [C-0805]  125.73 88.14 90 bottom
C900  100uF  [C-1210]  148.15 95.24 90 bottom
C943  330uF  [C-TAN-S7_3X4_3-H2]  264.67 89.74 180 bottom
C944  330uF  [C-TAN-S7_3X4_3-H2]  270.03 101.3 270 bottom
C945  330uF  [C-TAN-S7_3X4_3-H2]  270.01 89.74 180 bottom
C946  0.1uF  [S-C-0402]  153.03 101.35 270 top
C947  0.1uF  [S-C-0402]  283.1 93.89 90 bottom
C948  22uF  [C-0805]  273.86 95.3 180 bottom
C949  0.1uF  [S-C-0402]  281.6 89.39 180 bottom
C950  1nF  [S-C-0402]  285.1 94.89 270 bottom
C951  0.1uF  [S-C-0402]  283.6 95.39 180 bottom
C952  1uF  [S-C-0402]  281.6 91.39 180 bottom
C953  1uF  [S-C-0402]  285.6 89.39 0 bottom
C954  1uF  [S-C-0402]  286.1 90.89 90 bottom
C955  1uF  [S-C-0402]  279.1 94.89 90 bottom
C956  0.1uF  [S-C-0402]  280.6 98.39 180 bottom
C957  0.1uF  [S-C-0402]  289.1 90.89 90 bottom
C958  1nF  [S-C-0402]  288.6 98.39 180 bottom
C959  0.1uF  [S-C-0402]  280.1 86.89 270 bottom
C960  1nF  [S-C-0402]  287.6 94.39 0 bottom
C961  0.1uF  [S-C-0402]  288.6 87.39 0 bottom
C962  1nF  [S-C-0402]  288.1 88.89 270 bottom
C963  1uF  [S-C-0402]  280.1 89.89 270 bottom
C964  22uF  [C-0805]  269.14 96.72 0 bottom
C965  0.1uF  [S-C-0402]  153.03 104.27 270 top
C966  0.1uF  [S-C-0402]  284.6 90.39 180 bottom
C967  0.1uF  [S-C-0402]  284.6 88.39 180 bottom
C968  0.1uF  [S-C-0402]  285.1 95.89 270 bottom
C969  0.1uF  [S-C-0402]  282.6 88.39 180 bottom
C970  0.1uF  [S-C-0402]  287.1 96.89 90 bottom
C971  1nF  [S-C-0402]  281.1 87.89 90 bottom
C972  0.1uF  [S-C-0402]  287.1 87.89 90 bottom
C973  22uF  [C-0805]  285.18 104.84 180 bottom
C974  0.1uF  [S-C-0402]  191.61 117.24 180 bottom
C975  10uF  [S-C-0402]  285.1 93.89 270 bottom
C976  10uF  [S-C-0402]  285.1 92.89 90 bottom
C977  1uF  [S-C-0402]  280.1 90.89 90 bottom
C978  0.1uF  [S-C-0402]  288.1 89.89 90 bottom
C979  0.1uF  [S-C-0402]  281.1 93.89 90 bottom
C980  1nF  [S-C-0402]  286.6 95.39 180 bottom
C981  0.1uF  [S-C-0402]  281.1 94.89 270 bottom
C982  22uF  [C-0805]  273.8 106.83 180 bottom
C983  0.1uF  [S-C-0402]  266.75 107.34 0 bottom
C984  22uF  [C-0805]  279.5 81.66 270 bottom
C985  1nF  [S-C-0402]  126.21 100.86 90 bottom
C986  1UF  [S-C-0402]  283.1 92.89 90 bottom
C987  0.1uF  [S-C-0402]  106.81 117.79 180 bottom
C988  1nF  [S-C-0402]  288.6 96.39 0 bottom
C989  1uF  [S-C-0402]  279.6 96.39 0 bottom
C990  22uF  [C-0805]  293.38 104.33 180 bottom
C991  0.1uF  [S-C-0402]  191.48 120.92 0 bottom
C992  100nF  [C-0402S0]  91.34 65.33 270 top
C993  22uF  [C-0805]  91.46 63.81 270 top
C994  100nF  [C-0402S0]  91.74 72.37 90 top
C995  100nF  [C-0402S0]  96.67 65.33 90 top
C996  22uF  [C-0805]  96.42 63.81 90 top
C997  100nF  [C-0402S0]  96.82 72.37 270 top
C998  100nF  [C-0402S0]  96.67 65.31 270 bottom
C999  22uF  [C-0805]  96.42 63.78 270 bottom
C1000  100nF  [C-0402S0]  96.82 72.37 90 bottom
C1001  100nF  [C-0402S0]  91.34 65.31 90 bottom
C1002  22uF  [C-0805]  91.46 63.78 90 bottom
C1003  100nF  [C-0402S0]  91.74 72.37 270 bottom
C1004  100nF  [C-0402S0]  103.41 65.33 270 top
C1005  22uF  [C-0805]  103.54 63.81 270 top
C1006  100nF  [C-0402S0]  108.9 72.37 270 top
C1007  100nF  [C-0402S0]  108.75 65.33 90 top
C1008  22uF  [C-0805]  108.49 63.81 90 top
C1009  100nF  [C-0402S0]  103.82 72.37 90 top
C1010  100nF  [C-0402S0]  108.75 65.31 270 bottom
C1011  22uF  [C-0805]  108.49 63.78 270 bottom
C1012  100nF  [C-0402S0]  108.9 72.37 90 bottom
C1013  100nF  [C-0402S0]  103.41 65.31 90 bottom
C1014  22uF  [C-0805]  103.54 63.78 90 bottom
C1015  100nF  [C-0402S0]  103.82 72.37 270 bottom
C1016  100nF  [C-0402S0]  115.49 65.33 270 top
C1017  22uF  [C-0805]  115.62 63.81 270 top
C1018  100nF  [C-0402S0]  120.98 72.13 270 top
C1019  100nF  [C-0402S0]  120.82 65.33 90 top
C1020  22uF  [C-0805]  120.57 63.81 90 top
C1021  100nF  [C-0402S0]  115.9 72.12 90 top
C1022  100nF  [C-0402S0]  120.82 65.31 270 bottom
C1023  22uF  [C-0805]  120.57 63.78 270 bottom
C1024  100nF  [C-0402S0]  115.9 72.11 270 bottom
C1025  100nF  [C-0402S0]  115.49 65.31 90 bottom
C1026  22uF  [C-0805]  115.62 63.78 90 bottom
C1027  100nF  [C-0402S0]  120.98 72.11 90 bottom
C1028  100nF  [C-0402S0]  127.57 65.33 270 top
C1029  22uF  [C-0805]  127.69 63.81 270 top
C1030  100nF  [C-0402S0]  133.05 72.13 270 top
C1031  100nF  [C-0402S0]  132.9 65.33 90 top
C1032  22uF  [C-0805]  132.65 63.81 90 top
C1033  100nF  [C-0402S0]  127.97 72.12 90 top
C1034  100nF  [C-0402S0]  132.87 65.31 270 bottom
C1035  22uF  [C-0805]  132.65 63.78 270 bottom
C1036  100nF  [C-0402S0]  133.05 72.11 90 bottom
C1037  100nF  [C-0402S0]  127.57 65.31 90 bottom
C1038  22uF  [C-0805]  127.69 63.78 90 bottom
C1039  100nF  [C-0402S0]  127.97 72.11 270 bottom
C1040  100nF  [C-0402S0]  143.51 65.33 270 top
C1041  22uF  [C-0805]  143.64 63.81 270 top
C1042  100nF  [C-0402S0]  149 72.37 270 top
C1043  100nF  [C-0402S0]  148.84 65.33 90 top
C1044  22uF  [C-0805]  148.59 63.81 90 top
C1045  100nF  [C-0402S0]  143.92 72.37 90 top
C1046  100nF  [C-0402S0]  148.84 65.31 270 bottom
C1047  22uF  [C-0805]  148.59 63.78 270 bottom
C1048  100nF  [C-0402S0]  149 72.37 90 bottom
C1049  100nF  [C-0402S0]  143.51 65.31 90 bottom
C1050  22uF  [C-0805]  143.64 63.78 90 bottom
C1051  100nF  [C-0402S0]  143.92 72.37 270 bottom
C1052  100nF  [C-0402S0]  155.59 65.33 270 top
C1053  22uF  [C-0805]  155.71 63.81 270 top
C1054  100nF  [C-0402S0]  161.07 72.37 270 top
C1055  100nF  [C-0402S0]  160.92 65.33 90 top
C1056  22uF  [C-0805]  160.67 63.81 90 top
C1057  100nF  [C-0402S0]  155.99 72.37 90 top
C1058  100nF  [C-0402S0]  160.92 65.31 270 bottom
C1059  22uF  [C-0805]  160.67 63.78 270 bottom
C1060  100nF  [C-0402S0]  161.07 72.37 90 bottom
C1061  100nF  [C-0402S0]  155.59 65.31 90 bottom
C1062  22uF  [C-0805]  155.71 63.78 90 bottom
C1063  100nF  [C-0402S0]  155.99 72.37 270 bottom
C1064  100nF  [C-0402S0]  167.67 65.33 270 top
C1065  22uF  [C-0805]  167.79 63.81 270 top
C1066  100nF  [C-0402S0]  173.15 72.37 270 top
C1067  100nF  [C-0402S0]  173 65.33 90 top
C1068  22uF  [C-0805]  172.75 63.81 90 top
C1069  100nF  [C-0402S0]  168.07 72.37 90 top
C1070  100nF  [C-0402S0]  173 65.31 270 bottom
C1071  22uF  [C-0805]  172.75 63.78 270 bottom
C1072  100nF  [C-0402S0]  173.15 72.37 90 bottom
C1073  100nF  [C-0402S0]  167.67 65.31 90 bottom
C1074  22uF  [C-0805]  167.79 63.78 90 bottom
C1075  100nF  [C-0402S0]  168.07 72.37 270 bottom
C1076  100nF  [C-0402S0]  179.74 65.33 270 top
C1077  22uF  [C-0805]  179.87 63.81 270 top
C1078  100nF  [C-0402S0]  180.15 72.37 90 top
C1079  100nF  [C-0402S0]  185.08 65.33 90 top
C1080  22uF  [C-0805]  184.82 63.81 90 top
C1081  100nF  [C-0402S0]  185.23 72.37 270 top
C1082  100nF  [C-0402S0]  185.08 65.31 270 bottom
C1083  22uF  [C-0805]  184.82 63.78 270 bottom
C1084  100nF  [C-0402S0]  185.23 72.37 90 bottom
C1085  100nF  [C-0402S0]  179.74 65.31 90 bottom
C1086  22uF  [C-0805]  179.87 63.78 90 bottom
C1087  100nF  [C-0402S0]  180.15 72.37 270 bottom
C1088  100nF  [C-0402S0]  256.01 65.6 270 top
C1089  22uF  [C-0805]  256.14 64.08 270 top
C1090  100nF  [C-0402S0]  261.5 72.41 270 top
C1091  100nF  [C-0402S0]  261.34 65.6 90 top
C1092  22uF  [C-0805]  261.09 64.08 90 top
C1093  100nF  [C-0402S0]  256.42 72.41 90 top
C1094  100nF  [C-0402S0]  261.34 65.6 270 bottom
C1095  22uF  [C-0805]  261.09 64.08 270 bottom
C1096  100nF  [C-0402S0]  261.5 72.41 90 bottom
C1097  22uF  [C-0805]  256.14 64.08 90 bottom
C1098  100nF  [C-0402S0]  256.42 72.41 270 bottom
C1099  100nF  [C-0402S0]  256.01 65.6 90 bottom
C1100  100nF  [C-0402S0]  268.09 65.6 270 top
C1101  22uF  [C-0805]  268.21 64.08 270 top
C1102  100nF  [C-0402S0]  268.49 72.41 90 top
C1103  100nF  [C-0402S0]  273.42 65.6 90 top
C1104  22uF  [C-0805]  273.17 64.08 90 top
C1105  100nF  [C-0402S0]  273.57 72.41 270 top
C1106  100nF  [C-0402S0]  273.42 65.6 270 bottom
C1107  22uF  [C-0805]  273.17 64.08 270 bottom
C1108  100nF  [C-0402S0]  268.49 72.41 270 bottom
C1109  100nF  [C-0402S0]  268.09 65.6 90 bottom
C1110  22uF  [C-0805]  268.21 64.08 90 bottom
C1111  100nF  [C-0402S0]  273.57 72.41 90 bottom
C1184  100nF  [C-0402S0]  207.62 65.56 270 top
C1185  22uF  [C-0805]  207.74 64.04 270 top
C1186  100nF  [C-0402S0]  208.02 72.37 90 top
C1187  100nF  [C-0402S0]  212.95 65.56 90 top
C1188  22uF  [C-0805]  212.7 64.04 90 top
C1189  100nF  [C-0402S0]  213.1 72.37 270 top
C1190  100nF  [C-0402S0]  212.95 65.56 270 bottom
C1191  22uF  [C-0805]  212.7 64.04 270 bottom
C1192  100nF  [C-0402S0]  208.02 72.37 270 bottom
C1193  100nF  [C-0402S0]  207.62 65.56 90 bottom
C1194  22uF  [C-0805]  207.74 64.04 90 bottom
C1195  100nF  [C-0402S0]  213.1 72.37 90 bottom
C1196  100nF  [C-0402S0]  219.69 65.56 270 top
C1197  22uF  [C-0805]  219.82 64.04 270 top
C1198  100nF  [C-0402S0]  220.1 72.37 90 top
C1199  100nF  [C-0402S0]  225.03 65.56 90 top
C1200  22uF  [C-0805]  224.77 64.04 90 top
C1201  100nF  [C-0402S0]  225.18 72.37 270 top
C1202  100nF  [C-0402S0]  225.03 65.56 270 bottom
C1203  22uF  [C-0805]  224.77 64.04 270 bottom
C1204  100nF  [C-0402S0]  220.1 72.37 270 bottom
C1205  100nF  [C-0402S0]  219.69 65.56 90 bottom
C1206  22uF  [C-0805]  219.82 64.04 90 bottom
C1207  100nF  [C-0402S0]  225.18 72.37 90 bottom
C1208  100nF  [C-0402S0]  231.77 65.56 270 top
C1209  22uF  [C-0805]  231.9 64.04 270 top
C1210  100nF  [C-0402S0]  232.18 72.37 90 top
C1211  100nF  [C-0402S0]  237.1 65.56 90 top
C1212  22uF  [C-0805]  236.85 64.04 90 top
C1213  100nF  [C-0402S0]  237.26 72.37 270 top
C1214  100nF  [C-0402S0]  237.1 65.56 270 bottom
C1215  22uF  [C-0805]  236.85 64.04 270 bottom
C1216  100nF  [C-0402S0]  232.18 72.37 270 bottom
C1217  100nF  [C-0402S0]  231.77 65.56 90 bottom
C1218  22uF  [C-0805]  231.9 64.04 90 bottom
C1219  100nF  [C-0402S0]  237.26 72.37 90 bottom
C1220  100nF  [C-0402S0]  243.85 65.56 270 top
C1221  22uF  [C-0805]  243.97 64.04 270 top
C1222  100nF  [C-0402S0]  244.25 72.37 90 top
C1223  100nF  [C-0402S0]  249.18 65.56 90 top
C1224  22uF  [C-0805]  248.93 64.04 90 top
C1225  100nF  [C-0402S0]  249.33 72.37 270 top
C1226  100nF  [C-0402S0]  249.18 65.56 270 bottom
C1227  22uF  [C-0805]  248.93 64.04 270 bottom
C1228  100nF  [C-0402S0]  244.25 72.37 270 bottom
C1229  100nF  [C-0402S0]  243.85 65.56 90 bottom
C1230  22uF  [C-0805]  243.97 64.04 90 bottom
C1231  100nF  [C-0402S0]  249.33 72.37 90 bottom
C1232  100nF  [C-0402S0]  309.19 73.13 90 top
C1233  22uF  [C-0805]  309.06 74.78 90 top
C1234  100nF  [C-0402S0]  308.82 80.82 270 top
C1235  22uF  [C-0805]  308.92 82.44 270 top
C1236  100nF  [C-0402S0]  294.74 72.74 270 top
C1237  22uF  [C-0805]  295.03 74.38 270 top
C1238  100nF  [C-0402S0]  299.5 80.56 270 top
C1239  22uF  [C-0805]  300.99 83.43 0 top
C1240  100nF  [C-0402S0]  304.16 73.13 90 bottom
C1241  22uF  [C-0805]  304.49 74.78 90 bottom
C1242  100nF  [C-0402S0]  304.5 80.82 90 top
C1243  100nF  [C-0402S0]  299.95 72.88 90 top
C1244  22uF  [C-0805]  299.64 74.5 90 top
C1245  100nF  [C-0402S0]  299.5 80.56 90 bottom
C1246  100nF  [C-0402S0]  304.16 73.13 270 top
C1247  22uF  [C-0805]  304.49 74.78 270 top
C1248  100nF  [C-0402S0]  304.5 80.82 270 bottom
C1249  100nF  [C-0402S0]  299.95 72.88 270 bottom
C1250  22uF  [C-0805]  299.64 74.5 270 bottom
C1251  100nF  [C-0402S0]  295.37 80.41 90 top
C1252  100nF  [C-0402S0]  217.59 76.53 0 top
C1253  10uF  [C-0603S0]  96.91 75.49 270 top
C1254  10uF  [C-0603S0]  96.91 74.09 270 top
C1255  10uF  [C-0603S0]  96.91 75.49 90 bottom
C1256  10uF  [C-0603S0]  96.91 74.09 90 bottom
C1257  100nF  [C-0402S0]  205.51 76.53 0 top
C1258  10uF  [C-0603S0]  161.16 74.09 270 top
C1259  10uF  [C-0603S0]  161.16 75.49 270 top
C1260  10uF  [C-0603S0]  161.16 75.49 90 bottom
C1261  10uF  [C-0603S0]  161.16 74.09 90 bottom
C1262  100nF  [C-0402S0]  177.63 76.53 0 top
C1263  10uF  [C-0603S0]  237.34 75.49 270 top
C1264  10uF  [C-0603S0]  237.34 74.09 270 top
C1265  10uF  [C-0603S0]  237.34 75.49 90 bottom
C1266  10uF  [C-0603S0]  237.34 74.09 90 bottom
C1267  100nF  [C-0402S0]  268.14 75.99 90 top
C1268  10uF  [C-0603S0]  108.98 75.49 270 top
C1269  10uF  [C-0603S0]  108.98 74.09 270 top
C1270  10uF  [C-0603S0]  108.98 74.09 90 bottom
C1271  10uF  [C-0603S0]  108.98 75.49 90 bottom
C1272  100nF  [C-0402S0]  253.9 76.58 0 top
C1273  10uF  [C-0603S0]  173.24 75.49 270 top
C1274  10uF  [C-0603S0]  173.24 74.09 270 top
C1275  10uF  [C-0603S0]  173.24 75.49 90 bottom
C1276  10uF  [C-0603S0]  173.24 74.09 90 bottom
C1277  100nF  [C-0402S0]  241.74 76.53 0 top
C1278  10uF  [C-0603S0]  249.82 75.49 270 top
C1279  10uF  [C-0603S0]  249.82 74.09 270 top
C1280  10uF  [C-0603S0]  249.82 75.49 90 bottom
C1281  10uF  [C-0603S0]  249.82 74.09 90 bottom
C1282  100nF  [C-0402S0]  229.66 76.53 0 top
C1283  10uF  [C-0603S0]  121.06 73.84 270 top
C1284  10uF  [C-0603S0]  121.06 75.24 270 top
C1285  10uF  [C-0603S0]  121.06 75.24 90 bottom
C1286  10uF  [C-0603S0]  121.06 73.84 90 bottom
C1287  100nF  [C-0402S0]  306.7 91.48 270 top
C1288  10uF  [C-0603S0]  185.31 75.49 270 top
C1289  10uF  [C-0603S0]  185.31 74.09 270 top
C1290  10uF  [C-0603S0]  185.31 75.49 90 bottom
C1291  10uF  [C-0603S0]  185.31 74.09 90 bottom
C1292  100nF  [C-0402S0]  101.31 76.53 0 top
C1293  10uF  [C-0603S0]  261.58 75.54 270 top
C1294  10uF  [C-0603S0]  261.58 74.14 270 top
C1295  10uF  [C-0603S0]  261.58 74.01 90 bottom
C1296  10uF  [C-0603S0]  261.58 75.41 90 bottom
C1297  100nF  [C-0402S0]  89.23 76.53 0 top
C1298  10uF  [C-0603S0]  133.14 75.24 270 top
C1299  10uF  [C-0603S0]  133.14 73.84 270 top
C1300  10uF  [C-0603S0]  133.14 75.24 90 bottom
C1301  10uF  [C-0603S0]  133.14 73.84 90 bottom
C1302  100nF  [C-0402S0]  86.11 79.18 270 bottom
C1303  10uF  [C-0603S0]  213.19 75.49 270 top
C1304  10uF  [C-0603S0]  213.19 74.09 270 top
C1305  10uF  [C-0603S0]  213.19 74.09 90 bottom
C1306  10uF  [C-0603S0]  213.19 75.49 90 bottom
C1307  100nF  [C-0402S0]  120.62 148.12 0 bottom
C1308  10uF  [C-0603S0]  276.45 75.54 270 top
C1309  10uF  [C-0603S0]  276.45 74.14 270 top
C1310  10uF  [C-0603S0]  276.45 75.54 90 bottom
C1311  10uF  [C-0603S0]  276.45 74.14 90 bottom
C1312  100nF  [C-0402S0]  113.38 76.28 0 top
C1313  10uF  [C-0603S0]  149.08 74.09 270 top
C1314  10uF  [C-0603S0]  149.08 75.49 270 top
C1315  10uF  [C-0603S0]  149.08 75.49 90 bottom
C1316  10uF  [C-0603S0]  149.08 74.09 90 bottom
C1317  100nF  [C-0402S0]  110.24 109.4 180 bottom
C1318  10uF  [C-0603S0]  225.26 75.49 270 top
C1319  10uF  [C-0603S0]  225.26 74.09 270 top
C1320  10uF  [C-0603S0]  225.26 74.09 90 bottom
C1321  10uF  [C-0603S0]  225.26 75.49 90 bottom
C1332  100nF  [C-0402S0]  106.05 97.08 0 bottom
C1333  10uF  [C-0603S0]  308.06 84.07 90 bottom
C1334  10uF  [C-0603S0]  308.06 84.07 270 top
C1335  10uF  [C-0603S0]  303.35 84.07 90 top
C1336  10uF  [C-0603S0]  303.35 84.07 270 bottom
C1357  100nF  [S-C-0402]  127.89 27.82 270 bottom
C1358  100nF  [S-C-0402]  111.6 174.78 180 top
C1359  100nF  [S-C-0402]  114.07 27.87 270 bottom
C1360  100nF  [S-C-0402]  100.4 27.11 270 bottom
C1361  100nF  [S-C-0402]  202.64 26.87 270 bottom
C1362  100nF  [S-C-0402]  184.97 27.71 270 bottom
C1363  100nF  [S-C-0402]  171.83 27.87 270 bottom
C1364  100nF  [S-C-0402]  142.74 27.87 270 bottom
C1365  100nF  [S-C-0402]  260.04 27.76 270 bottom
C1366  100nF  [S-C-0402]  245.94 27.76 270 bottom
C1367  100nF  [S-C-0402]  232.11 27.33 0 bottom
C1368  100nF  [S-C-0402]  103.48 191.99 0 top
C1369  1UF  [S-C-0402]  55.7 78.49 180 top
C1370  10uF  [S-C-0402]  54.68 78.49 0 top
C1371  1UF  [S-C-0402]  100.52 137.74 0 top
C1372  100nF  [S-C-0402]  157.05 27.87 90 bottom
C1373  100nF  [S-C-0402]  135.39 181.34 180 top
C1374  100nF  [S-C-0402]  101.6 11.35 0 bottom
C1375  100nF  [S-C-0402]  86.29 28.29 0 bottom
C1377  100nF  [C-0402S0]  87 188.34 90 top
C1378  100nF  [S-C-0402]  295.61 40.28 90 bottom
C1379  100nF  [S-C-0402]  274.57 26.42 90 bottom
C1380  1UF  [S-C-0402]  103.06 137.36 180 top
C1381  10uF  [C-0603S0]  104.29 137.85 0 top
C1382  1UF  [S-C-0402]  64.64 79.43 180 bottom
C1383  22uF  [C-0805]  114.43 139.7 0 top
C1384  0.1uF  [S-C-0402]  110.29 126.44 270 bottom
C1385  0.1uF  [S-C-0402]  110.29 125.5 270 bottom
C1386  0.1uF  [S-C-0402]  109.12 128.55 0 bottom
C1387  1nF  [S-C-0402]  135.21 98.86 90 bottom
C1388  0.1uF  [S-C-0402]  114.81 129.22 180 bottom
C1389  1UF  [S-C-0402]  110.74 129.11 0 bottom
C1390  0.1uF  [S-C-0402]  112.2 126.45 90 bottom
C1391  1UF  [S-C-0402]  114.81 123.63 180 bottom
C1392  1UF  [S-C-0402]  113.51 86.04 270 bottom
C1393  22uF  [C-0805]  121.66 131.5 0 bottom
C1394  0.1uF  [S-C-0402]  114.81 125.66 0 bottom
C1395  0.1uF  [S-C-0402]  110.39 124.05 270 bottom
C1396  0.1uF  [S-C-0402]  116.4 133.49 270 bottom
C1397  1nF  [S-C-0402]  282.6 90.39 0 bottom
C1398  0.1uF  [S-C-0402]  116.84 134.9 270 bottom
C1399  1UF  [S-C-0402]  110.29 127.38 90 bottom
C1400  1UF  [S-C-0402]  116.33 127.18 90 bottom
C1401  0.1uF  [S-C-0402]  119.25 127.31 90 bottom
C1402  1UF  [S-C-0402]  114.81 130.99 180 bottom
C1403  100nF  [C-0402S0]  165.56 76.53 0 top
C1404  0.1uF  [S-C-0402]  135.21 99.86 270 bottom
